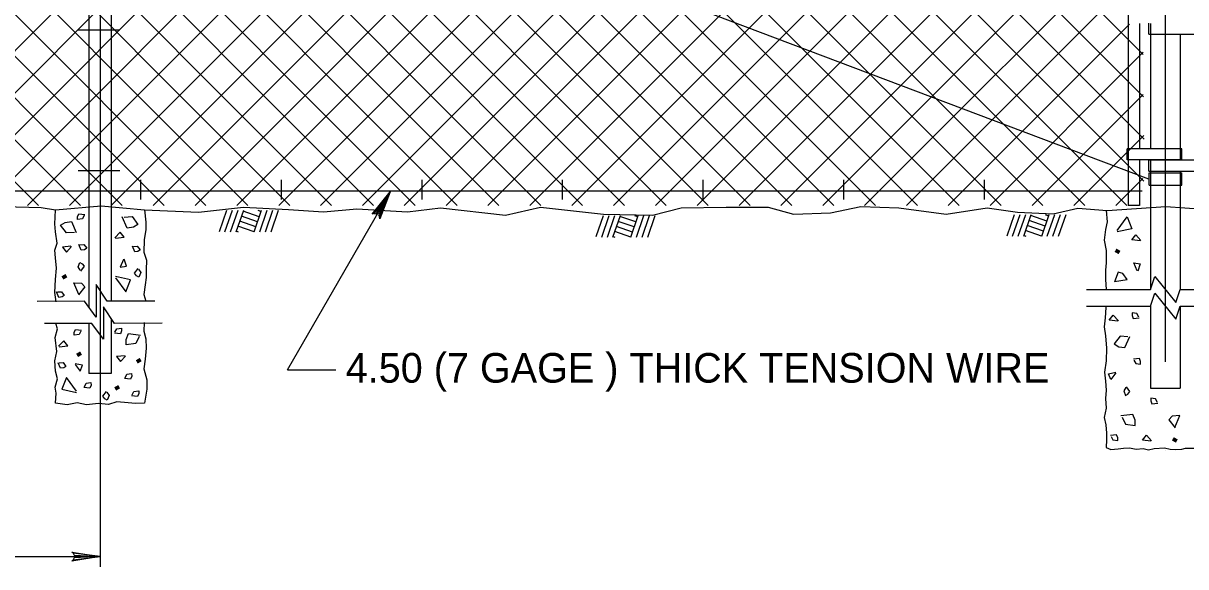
# Model space of a CAD drawing. Extents: x 13 to 918, y -903 to 879.
# Drawn here: x 455.7 to 578.5, y -20.3 to 37 of the extents above; entities that cross this region are included whole.
import ezdxf

# ---------------------------------------------------------------- set-up
doc = ezdxf.new("R2010")
doc.units = 0
for name, color, linetype in [('1', 7, 'Continuous'), ('2', 7, 'Continuous'), ('3', 7, 'Continuous')]:
    doc.layers.add(name, color=color, linetype=linetype)

msp = doc.modelspace()

# ---------------------------------------------------------------- linework, layer by layer
at = {"layer": '1'}
for p, q in [((477.208, 17.2905), (476.435, 15.0635)), ((477.80375, 17.2905), (477.01625, 15.02175)), ((478.3995, 17.2905), (477.612, 15.02175)), ((478.9955, 17.2905), (478.208, 15.02175)), ((480.6725, 16.649), (478.97675, 17.2365)), ((480.87675, 17.2905), (480.09125, 15.02175)), ((480.85575, 17.18025), (480.54125, 17.2905)), ((481.4725, 17.2905), (480.687, 15.02175)), ((482.06625, 17.2905), (481.283, 15.02175)), ((482.66425, 17.2905), (481.87875, 15.02175)), ((480.30575, 15.5865), (478.608, 16.17175)), ((480.48925, 16.11775), (478.79325, 16.70725)), ((516.99125, 16.73425), (516.21825, 14.50725)), ((517.587, 16.73425), (516.7995, 14.4655)), ((518.183, 16.73425), (517.3955, 14.4655)), ((518.77875, 16.73425), (517.99125, 14.4655)), ((520.2725, 15.5615), (518.57675, 16.151)), ((520.45575, 16.09275), (518.76, 16.68025)), ((520.66, 16.73425), (519.8745, 14.4655)), ((520.63925, 16.624), (520.3245, 16.73425)), ((521.25575, 16.73425), (520.4705, 14.4655)), ((521.8495, 16.73425), (521.06625, 14.4655)), ((522.4475, 16.73425), (521.662, 14.4655)), ((560.38075, 16.828), (559.608, 14.601)), ((560.97675, 16.828), (560.18925, 14.55925)), ((561.5725, 16.828), (560.785, 14.55925)), ((562.16825, 16.828), (561.38075, 14.55925)), ((563.662, 15.65525), (561.96625, 16.24475)), ((563.8455, 16.1865), (562.1495, 16.774)), ((564.0495, 16.828), (563.26425, 14.55925)), ((564.02875, 16.71775), (563.71425, 16.828)), ((564.6455, 16.828), (563.86, 14.55925)), ((565.23925, 16.828), (564.45575, 14.55925)), ((565.837, 16.828), (565.05175, 14.55925)), ((478.487, 15.02175), (478.23925, 15.10925)), ((480.1205, 15.05525), (478.4225, 15.6405)), ((519.90375, 14.499), (518.20575, 15.08425)), ((520.08925, 15.03025), (518.39125, 15.6155)), ((563.29325, 14.59275), (561.5955, 15.178)), ((563.47875, 15.124), (561.78075, 15.70925)), ((518.2705, 14.4655), (518.0225, 14.553)), ((561.66, 14.55925), (561.412, 14.64675))]:
    msp.add_line(p, q, dxfattribs=at)
at = {"layer": '2'}
for p, q in [((576.35375, 84.74475), (576.35375, 1.33025)), ((572.44125, 83.18225), (572.44125, 17.81775)), ((463.85375, 81.88225), (463.85375, -20.274)), ((463.85375, 80.85925), (463.85375, 21.351)), ((462.67875, 76.4615), (462.67875, 7.05525)), ((465.02875, 76.4615), (465.02875, 7.6865)), ((574.63075, 20.59675), (482.76425, 55.28225)), ((573.61625, 37.01975), (573.61625, 23.8135)), ((574.61425, 35.901), (574.61425, 37.076)), ((574.79125, 37.0385), (574.79125, 23.79475)), ((465.937, 36.324), (461.5475, 36.324)), ((574.61425, 35.901), (580.37675, 35.901)), ((576.35375, 36.4885), (576.35375, 36.4885)), ((576.35375, 36.4885), (576.35375, 36.4885)), ((576.35375, 36.4885), (576.35375, 36.4885)), ((577.91625, 35.85525), (577.91625, 22.6115)), ((578.09325, 23.8155), (572.33075, 23.8155)), ((572.33075, 22.6405), (572.33075, 23.8155)), ((574.79125, 23.8155), (574.79125, 23.8155)), ((578.09325, 22.6405), (578.09325, 23.8155)), ((578.09325, 22.6405), (572.33075, 22.6405)), ((573.61625, 22.63025), (573.61625, 17.81775)), ((574.61425, 22.6405), (580.37675, 22.6405)), ((574.61425, 21.4655), (574.61425, 22.6405)), ((574.79125, 22.63025), (574.79125, 8.9655)), ((576.35375, 23.228), (576.35375, 23.228)), ((577.91625, 22.6405), (577.91625, 22.6405)), ((577.91625, 22.6405), (577.91625, 22.6405)), ((465.937, 21.48025), (461.5475, 21.48025)), ((574.61425, 21.4655), (580.37675, 21.4655)), ((574.637, 21.25725), (578.09325, 21.25725)), ((574.637, 19.95725), (574.637, 21.25725)), ((574.79125, 21.4655), (574.79125, 21.4655)), ((576.35375, 22.053), (576.35375, 22.053)), ((576.35375, 22.053), (576.35375, 22.053)), ((577.91625, 21.4655), (577.91625, 8.9655)), ((578.09325, 19.95725), (578.09325, 21.25725)), ((468.17675, 18.46975), (468.17675, 20.549)), ((483.0205, 18.46975), (483.0205, 20.549)), ((497.86625, 18.46975), (497.86625, 20.549)), ((512.712, 18.46975), (512.712, 20.549)), ((527.55575, 18.46975), (527.55575, 20.549)), ((542.40175, 18.46975), (542.40175, 20.549)), ((557.2455, 18.46975), (557.2455, 20.549)), ((574.637, 19.95725), (578.09325, 19.95725)), ((576.35375, 20.60725), (576.35375, 20.60725)), ((576.35375, 20.60725), (576.35375, 20.60725)), ((129.09125, 19.38225), (573.912, 19.38225)), ((483.66425, 0.48425), (494.50375, 19.25725)), ((459.16, 17.29675), (459.16, 17.29675)), ((463.85375, 17.29675), (463.85375, 17.29675)), ((463.85375, 17.29675), (463.85375, 17.29675)), ((468.5495, 17.29675), (468.5495, 17.29675)), ((570.22875, 17.29675), (570.22875, 17.29675)), ((573.61625, 17.81775), (572.44125, 17.81775)), ((576.35375, 17.29675), (576.35375, 17.29675)), ((576.35375, 17.29675), (576.35375, 17.29675)), ((574.79125, 8.9655), (575.23075, 10.3385)), ((575.23075, 10.3385), (577.47675, 7.59275)), ((568.0225, 8.9655), (574.79125, 8.9655)), ((577.47675, 7.59275), (577.91625, 8.9655)), ((577.91625, 8.9655), (584.683, 8.9655)), ((574.79125, 7.20925), (575.23075, 8.58225)), ((575.23075, 8.58225), (577.47675, 5.8365)), ((568.0225, 7.20925), (574.79125, 7.20925)), ((574.79125, 7.20925), (574.79125, -1.45325)), ((577.47675, 5.8365), (577.91625, 7.20925)), ((577.91625, 7.20925), (584.683, 7.20925)), ((577.91625, 7.20925), (577.91625, -1.45325)), ((462.67875, 5.35725), (462.67875, 0.10925)), ((465.02875, 5.83425), (465.02875, 0.10925)), ((465.02875, 0.10925), (462.67875, 0.10925)), ((483.66425, 0.48425), (488.7725, 0.48425)), ((574.79125, -1.45325), (577.91625, -1.45325)), ((463.85375, -3.04075), (463.85375, -3.04075)), ((576.35375, -7.96575), (576.35375, -7.96575)), ((351.437, -19.20525), (463.85375, -19.20525))]:
    msp.add_line(p, q, dxfattribs=at)
for points in [[(461.79125, 17.81775), (396.42675, 83.18225)], [(466.21, 17.81775), (400.8455, 83.18225)], [(470.62875, 17.81775), (405.26425, 83.18225)], [(475.0475, 17.81775), (409.683, 83.18225)], [(479.46625, 17.81775), (414.10175, 83.18225)], [(483.885, 17.81775), (418.5205, 83.18225)], [(488.30575, 17.81775), (422.94125, 83.18225)], [(492.7245, 17.81775), (427.36, 83.18225)], [(497.14325, 17.81775), (431.77875, 83.18225)], [(501.56425, 17.81775), (436.1995, 83.18225)], [(438.533, 17.81775), (503.8975, 83.18225)], [(505.983, 17.81775), (440.61825, 83.18225)], [(442.95375, 17.81775), (508.31825, 83.18225)], [(510.40175, 17.81775), (445.037, 83.18225)], [(447.3725, 17.81775), (512.737, 83.18225)], [(514.8225, 17.81775), (449.458, 83.18225)], [(451.79125, 17.81775), (517.15575, 83.18225)], [(519.24125, 17.81775), (453.87675, 83.18225)], [(456.212, 17.81775), (521.57675, 83.18225)], [(523.66, 17.81775), (458.2955, 83.18225)], [(460.63075, 17.81775), (525.9955, 83.18225)], [(528.08075, 17.81775), (462.71625, 83.18225)], [(465.0495, 17.81775), (530.41425, 83.18225)], [(532.4995, 17.81775), (467.135, 83.18225)], [(469.4705, 17.81775), (534.835, 83.18225)], [(536.91825, 17.81775), (471.55375, 83.18225)], [(473.88925, 17.81775), (539.25375, 83.18225)], [(541.337, 17.81775), (475.9745, 83.18225)], [(478.308, 17.81775), (543.6725, 83.18225)], [(545.758, 17.8155), (480.39325, 83.18225)], [(482.72675, 17.81775), (548.09125, 83.18225)], [(550.17675, 17.81775), (484.812, 83.18225)], [(487.1475, 17.81775), (552.512, 83.18225)], [(554.5955, 17.81775), (489.233, 83.18225)], [(491.56625, 17.81775), (556.93075, 83.18225)], [(559.01625, 17.8155), (493.65175, 83.18225)], [(495.985, 17.81775), (561.3495, 83.18225)], [(563.435, 17.81775), (498.0705, 83.18225)], [(500.40575, 17.81775), (565.7705, 83.18225)], [(567.85575, 17.8155), (502.49125, 83.18225)], [(504.8245, 17.81775), (570.18925, 83.18225)], [(572.2745, 17.81775), (506.91, 83.18225)], [(574.0995, 20.4115), (511.32875, 83.18225)], [(574.1245, 24.80725), (515.7495, 83.18225)], [(574.05375, 29.299), (520.16825, 83.18225)], [(574.03075, 33.7405), (524.587, 83.18225)], [(509.24325, 17.81775), (572.47875, 81.053)], [(513.66425, 17.81775), (574.058, 78.2115)], [(518.08075, 17.8155), (574.06425, 73.799)], [(457.3705, 17.81775), (404.29975, 70.88825)], [(522.50175, 17.81775), (574.04125, 69.35525)], [(526.9225, 17.81775), (574.0745, 64.96975)], [(531.34125, 17.81775), (574.108, 60.58425)], [(535.76, 17.81775), (574.008, 56.0655)], [(540.17875, 17.8155), (573.85375, 51.4905)], [(544.5995, 17.81775), (574.0495, 47.26775)], [(549.01825, 17.81775), (574.0245, 42.824)], [(553.43925, 17.81775), (572.562, 36.9405)], [(557.858, 17.81775), (574.02675, 33.9865)], [(562.27675, 17.81775), (574.00375, 29.54275)], [(566.6975, 17.81775), (574.0955, 25.2155)], [(571.11425, 17.8155), (573.985, 20.6865)], [(453.69325, 17.70525), (457.6245, 17.63025), (459.16625, 17.38025), (463.98075, 17.78225), (468.54125, 17.38025), (474.26825, 17.1135), (479.0205, 17.649), (483.7725, 17.401), (487.45575, 17.153), (490.96825, 17.476), (496.312, 17.153), (499.8225, 17.57175), (506.6745, 16.80925), (510.358, 17.649)], [(459.21425, 7.65525), (459.06625, 8.65925), (459.14325, 10.03425), (459.258, 11.2155), (459.14325, 12.30525), (459.06625, 13.10525), (459.333, 13.851), (459.14325, 15.03425), (459.06625, 15.89275), (459.10375, 16.599), (459.16625, 17.38025)], [(468.54125, 17.38025), (468.685, 16.08425), (468.685, 15.301), (468.533, 14.19475), (468.49325, 12.89675), (468.762, 12.076), (468.7225, 11.026), (468.7225, 10.224), (468.608, 9.44275), (468.49325, 8.43025), (468.70575, 7.7385)], [(510.358, 17.649), (517.037, 16.903), (522.21, 16.80925), (525.22675, 17.57175), (529.97875, 17.649), (534.4245, 17.649), (537.0975, 16.903), (541.01, 17.05725), (544.1975, 17.724), (548.20375, 17.57175), (553.2245, 16.903), (557.55575, 17.57175), (560.762, 17.13225), (564.5225, 16.9615), (567.11825, 17.553), (570.22875, 17.29675), (576.39325, 17.724), (582.4205, 17.29675)], [(570.10375, 17.29675), (570.21625, 16.12175), (570.02675, 15.301), (569.912, 14.174), (570.1205, 13.0865), (570.1205, 11.7885), (570.0455, 11.00725), (570.02675, 10.0135), (570.11625, 8.98025)], [(461.1455, 14.99275), (460.3205, 14.9385), (459.69125, 15.74675), (460.1705, 16.04275), (460.84125, 16.13425), (461.35375, 14.9635)], [(462.18075, 16.799), (461.9995, 16.428), (461.48925, 16.35525), (461.48075, 16.6365), (461.61, 16.951), (462.2455, 16.878)], [(466.41, 16.599), (467.23925, 16.653), (467.86425, 15.8405), (467.385, 15.54475), (466.7225, 15.453), (466.21, 16.628)], [(571.26425, 15.1865), (572.335, 16.6365), (572.83075, 15.378), (571.26425, 15.03225)], [(465.50175, 14.378), (466.3975, 14.478), (465.97675, 15.00725), (465.435, 14.41775)], [(573.7205, 14.10925), (572.8245, 14.20925), (573.2455, 14.7385), (573.787, 14.149)], [(460.787, 13.54275), (459.88925, 13.44275), (460.31, 12.9135), (460.85375, 13.503)], [(461.7205, 13.69275), (462.133, 13.71975), (462.4475, 13.3135), (462.208, 13.1655), (461.8725, 13.12175), (461.61825, 13.70525)], [(467.37875, 13.51775), (467.79125, 13.54475), (468.10575, 13.1385), (467.86625, 12.9905), (467.53075, 12.94675), (467.27675, 13.53025)], [(461.76425, 11.001), (461.533, 11.34475), (461.72675, 11.81975), (461.9745, 11.6865), (462.183, 11.41975), (461.80375, 10.90525)], [(466.3475, 12.14275), (465.985, 11.3155), (466.65375, 11.4155), (466.41425, 12.18025)], [(467.92875, 11.099), (468.158, 10.75525), (467.96625, 10.278), (467.71825, 10.4115), (467.51, 10.68025), (467.89125, 11.19475)], [(573.39325, 10.949), (573.033, 11.776), (573.70175, 11.676), (573.46, 10.9115)], [(465.4975, 10.18025), (466.56825, 8.726), (467.06425, 9.98425), (465.50175, 10.33425)], [(570.99325, 9.8135), (572.335, 10.00525), (571.88075, 10.66775), (571.37675, 10.78025), (570.9725, 9.776)], [(469.658, 7.74275), (464.61825, 7.724), (463.45575, 9.478), (463.45575, 6.0635), (462.233, 7.724), (457.21425, 7.703)], [(459.36, 8.70925), (459.7725, 8.7365), (460.087, 8.33025), (459.8475, 8.18225), (459.512, 8.1385), (459.258, 8.72175)], [(461.608, 8.426), (461.10375, 9.68425), (461.90375, 9.62175), (462.25375, 9.24275), (461.583, 8.3885)], [(470.4225, 5.4155), (465.383, 5.39675), (464.2205, 7.151), (464.2205, 3.7365), (462.9975, 5.39675), (457.97875, 5.376)], [(570.10375, 7.21775), (570.083, 7.076), (569.987, 5.9865), (569.89125, 5.03225), (570.0455, 4.078), (570.16, 2.78025), (570.1205, 1.44475), (569.9495, 0.2615), (570.0455, -0.7115), (570.1205, -1.66575), (570.02675, -2.54475), (570.1205, -3.5365), (569.89125, -4.52825), (570.083, -5.3115), (570.16, -6.1885), (570.16, -6.876), (570.10375, -7.70325), (570.5975, -7.90725), (571.38075, -7.83025), (571.935, -7.774), (572.583, -7.7345), (573.28925, -7.86775), (574.01425, -7.79275), (574.587, -7.94475), (575.17875, -7.79275), (576.26625, -7.7345), (576.87675, -7.86775), (577.39325, -7.90725), (578.0995, -7.86775), (578.48075, -7.774), (579.4725, -7.774)], [(571.335, 5.6155), (570.43925, 5.7155), (570.86, 6.24475), (571.40175, 5.65525)], [(573.5455, 6.051), (573.362, 6.42175), (572.85375, 6.4905), (572.8455, 6.20925), (572.9725, 5.899), (573.608, 5.96975)], [(468.535, 5.4865), (468.533, 5.47175), (468.49325, 4.574), (468.685, 3.75525), (468.7225, 2.7615), (468.608, 1.61775), (468.49325, 0.60525), (468.7995, -0.57825), (468.7995, -1.551), (468.685, -2.18025), (468.54125, -3.01575), (467.5975, -3.0595), (466.833, -2.98225), (465.63075, -2.8865), (464.75375, -3.174), (463.70375, -3.0595), (462.44325, -3.2115), (461.45175, -2.98225), (460.40175, -3.2115), (459.16625, -3.01575), (459.21825, -1.95325), (459.10375, -1.322), (459.3725, -0.4635), (459.14325, 0.35725), (459.06625, 1.426), (459.2955, 2.41775), (459.10375, 3.90725), (459.3725, 4.803), (459.18075, 5.39475), (459.18075, 5.4155)], [(461.8205, 4.5885), (461.637, 4.21775), (461.12875, 4.14475), (461.1205, 4.426), (461.2495, 4.74275), (461.885, 4.66975)], [(465.435, 4.453), (465.61825, 4.824), (466.12675, 4.89275), (466.135, 4.6115), (466.00575, 4.299), (465.3725, 4.36975)], [(468.00575, 4.003), (467.63925, 3.2615), (466.6225, 3.11975), (466.60575, 3.68225), (466.86425, 4.3115), (468.135, 4.1655)], [(572.408, 3.98025), (571.57875, 4.03425), (570.95375, 3.22175), (571.433, 2.926), (572.0955, 2.83425), (572.608, 4.00925)], [(459.5495, 2.9365), (460.4455, 3.0365), (460.0245, 3.5655), (459.483, 2.976)], [(459.535, 1.23425), (459.9475, 1.2615), (460.262, 0.85525), (460.0225, 0.70725), (459.687, 0.6635), (459.433, 1.24675)], [(466.4955, 1.9865), (465.5975, 1.8865), (466.01825, 1.35725), (466.562, 1.94675)], [(573.04325, 1.528), (573.2245, 1.15725), (573.735, 1.08425), (573.74325, 1.3655), (573.61425, 1.68025), (572.97875, 1.60725)], [(461.23925, 1.0655), (461.7745, 0.3405), (462.0225, 0.96975), (461.24125, 1.14275)], [(466.4995, -0.34075), (466.683, 0.03025), (467.19125, 0.099), (467.1995, -0.18225), (467.0725, -0.49275), (466.437, -0.422)], [(571.137, 0.18425), (570.60175, -0.54075), (570.35375, 0.0885), (571.135, 0.2615)], [(461.385, -1.751), (460.31425, -0.301), (459.81825, -1.5595), (461.385, -1.90525)], [(462.20375, -1.29475), (462.387, -0.924), (462.8955, -0.85525), (462.90375, -1.1365), (462.77675, -1.447), (462.14125, -1.376)], [(464.58075, -1.872), (464.81, -2.21575), (464.61825, -2.69275), (464.3705, -2.5595), (464.162, -2.29075), (464.54325, -1.776)], [(467.2455, -2.15725), (467.42875, -1.7845), (467.937, -1.71575), (467.9455, -1.997), (467.81825, -2.3095), (467.183, -2.2385)], [(572.20175, -1.38025), (571.9725, -1.724), (572.16425, -2.201), (572.412, -2.06775), (572.6205, -1.799), (572.23925, -1.2845)], [(575.51425, -2.94475), (575.33075, -2.574), (574.8225, -2.50525), (574.81425, -2.7865), (574.94325, -3.099), (575.57675, -3.02825)], [(571.783, -4.5095), (572.1495, -5.251), (573.16625, -5.39275), (573.183, -4.83025), (572.9245, -4.201), (571.65375, -4.347)], [(577.36825, -5.59475), (577.8725, -4.3365), (577.0725, -4.399), (576.7225, -4.77825), (577.39325, -5.63225)], [(570.6455, -6.52825), (570.82875, -6.899), (571.337, -6.972), (571.3455, -6.69075), (571.21625, -6.374), (570.58075, -6.447)], [(574.82675, -7.01775), (573.93075, -6.91775), (574.35175, -6.3885), (574.89325, -6.97825)]]:
    msp.add_lwpolyline(points, dxfattribs=at)
at = {"layer": '3'}
for points in [[(492.77675, 16.978), (493.008, 16.9655), (494.50375, 19.25725), (492.77675, 16.978), (492.5955, 16.9135), (494.50375, 19.25725), (493.25575, 16.826), (493.38075, 16.6385), (494.50375, 19.25725), (493.4225, 16.4365), (493.38075, 16.6385)], [(492.77675, 16.978), (493.008, 16.9655), (494.50375, 19.25725), (492.77675, 16.978), (492.5955, 16.9135), (494.50375, 19.25725), (493.25575, 16.826), (493.38075, 16.6385), (494.50375, 19.25725), (493.4225, 16.4365), (493.38075, 16.6385)], [(461.01625, -18.849), (461.1225, -19.05525), (463.85375, -19.20525), (461.01625, -18.849), (460.8705, -18.724), (463.85375, -19.20525), (461.1245, -19.34075), (461.0245, -19.54275), (463.85375, -19.20525), (460.8705, -19.68025), (461.0245, -19.54275)]]:
    msp.add_lwpolyline(points, dxfattribs=at)

# ---------------------------------------------------------------- texts
at = {"layer": '2'}
for rotation, p in [(60, (571.22875, 12.3635)), (300.2283778, (459.59125, 10.6885)), (300.2283778, (461.14125, 2.5155)), (300.2283778, (467.44125, 1.83425)), (300.2283778, (465.162, -1.026)), (60, (577.27875, -7.524))]:
    msp.add_text('.', height=3.125, rotation=rotation, dxfattribs=at).set_placement(p)
at = {"layer": '3'}
msp.add_text('4.50 (7 GAGE ) THICK TENSION WIRE', height=3.1249995, dxfattribs=at).set_placement((489.80575, -0.8595))

doc.saveas('drawing.dxf')
